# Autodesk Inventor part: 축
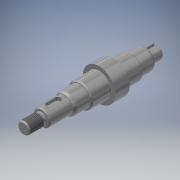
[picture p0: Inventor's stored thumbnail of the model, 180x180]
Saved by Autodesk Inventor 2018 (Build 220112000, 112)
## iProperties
Created: 2019-09
Part Number: 축
Material: 강철, 연강
Document SubType Name: Modeling
Designer: mduedu
Density: 7.86 g/cm^3
Mass: 210.278 g
Surface Area: 69.4764 cm^2
Volume: 26.7529 cm^3
Appearance: 강철
Author: mduedu
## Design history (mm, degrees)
sketch "스케치1"
  geometry: L1 (0, 0)-(15, 0); L2 (15, 0)-(15, 5); L3 (15, 5)-(0, 5); L4 (0, 5)-(0, 0); L5 (15, 0)-(34, 0); L6 (34, 0)-(34, 7); L7 (34, 7)-(15, 7); L8 (15, 7)-(15, 0); L9 (34, 0)-(47, 0); L10 (47, 0)-(47, 8.5); L11 (47, 8.5)-(34, 8.5); L12 (34, 8.5)-(34, 0); L13 (47, 0)-(63, 0); L14 (63, 0)-(63, 10); L15 (63, 10)-(47, 10); L16 (47, 10)-(47, 0); L17 (63, 0)-(75, 0); L18 (75, 0)-(75, 13.5); L19 (75, 13.5)-(63, 13.5); L20 (63, 13.5)-(63, 0); L21 (75, 0)-(90, 0); L22 (90, 0)-(90, 10); L23 (90, 10)-(75, 10); L24 (75, 10)-(75, 0); L25 (90, 0)-(102, 0); L26 (102, 0)-(102, 8.5); L27 (102, 8.5)-(90, 8.5); L28 (90, 8.5)-(90, 0); L29 (102, 0)-(111, 0); L30 (111, 0)-(111, 5.5); L31 (111, 5.5)-(102, 5.5); L32 (102, 5.5)-(102, 0)
  constraints: 64 end point, 16 parallel, 8 horizontal, 8 perpendicular
  dimensions: "d0" = 111 distance between parallel lines of L30 L4; "d2" = 15 distance of L2.end L3.end; "d3" = 19 distance of L6.end L7.end; "d4" = 12 distance of L18.end L19.end; "d5" = 15 distance of L22.end L23.end; "d6" = 12 distance of L26.end L27.end; "d7" = 9 distance of L30.end L31.end; "d8" = 16 distance of L14.end L15.end; "d9" = 10 diameter of L3 L1; "d10" = 14 diameter of L7 L5; "d11" = 17 diameter of L11 L9; "d12" = 20 diameter of L15 L13; "d13" = 27 diameter of L19 L17; "d14" = 20 diameter of L23 L21; "d15" = 17 diameter of L27 L25; "d16" = 11 diameter of L31 L29
revolve "회전1" sketch "스케치1" stored, may be unused: angle "d17" = 90 deg
sketch "스케치2"
  geometry: L1 (0, -5)-(0, 5) reference; L2 (0, 5)-(15, 5) reference; L3 (15, 5)-(15, 7) reference; L4 (15, 7)-(34, 7) reference; L5 (34, 7)-(34, 8.5) reference; L6 (34, 8.5)-(47, 8.5) reference; L7 (47, 8.5)-(47, 10) reference; L8 (47, 10)-(63, 10) reference; L9 (63, 10)-(63, 13.5) reference; L10 (63, 13.5)-(75, 13.5) reference; L11 (75, 13.5)-(75, 10) reference; L12 (75, 10)-(90, 10) reference; L13 (90, 10)-(90, 8.5) reference; L14 (90, 8.5)-(102, 8.5) reference; L15 (102, 8.5)-(102, 5.5) reference; L16 (102, 5.5)-(111, 5.5) reference; L17 (111, 5.5)-(111, -5.5) reference; L18 (111, -5.5)-(102, -5.5) reference; L19 (102, -5.5)-(102, -8.5) reference; L20 (102, -8.5)-(90, -8.5) reference; L21 (90, -8.5)-(90, -10) reference; L22 (90, -10)-(75, -10) reference; L23 (75, -10)-(75, -13.5) reference; L24 (75, -13.5)-(63, -13.5) reference; L25 (63, -13.5)-(63, -10) reference; L26 (63, -10)-(47, -10) reference; L27 (47, -10)-(47, -8.5) reference; L28 (47, -8.5)-(34, -8.5) reference; L29 (34, -8.5)-(34, -7) reference; L30 (34, -7)-(15, -7) reference; L31 (15, -7)-(15, -5) reference; L32 (15, -5)-(0, -5) reference; L33 (0, 0)-(111, 0); L34 (15, 5)-(12.014, 5); L35 (13.4, 4.2)-(15, 4.2); L36 (15, 4.2)-(15, 5); L37 (12.014, 5)-(13.4, 4.2)
  constraints: 10 end point, 1 horizontal, 1 midpoint, 1 parallel, 1 vertical
  dimensions: "d18" = 30 deg angle of L2 L37; "d19" = 8.4 diameter of L35 L33; "d21" = 2.986 distance from line of L34.end L36
revolve "회전2" sketch "스케치2" stored, may be unused: angle "d22" = 90 deg
fillet "모깎기1" dims "d23" = 0.6
feature "스레드1" dims "d24" = 10, "d25" = 0
chamfer "모따기1" distance "d26" = 1; stored, may be unused: second distance "d27" = 2, angle "d28" = 45 deg
chamfer "모따기2" distance "d29" = 1; stored, may be unused: second distance "d30" = 2, angle "d31" = 45 deg
chamfer "모따기3" distance "d32" = 1.819; stored, may be unused: second distance "d33" = 2, angle "d34" = 30 deg
fillet "모깎기2" dims "d35" = 2
chamfer "모따기4" distance "d36" = 1; stored, may be unused: second distance "d37" = 2, angle "d38" = 30 deg
fillet "모깎기3" dims "d39" = 0.3
chamfer "모따기5" distance "d40" = 1; stored, may be unused: second distance "d41" = 2, angle "d42" = 30 deg
chamfer "모따기6" distance "d43" = 1.819; stored, may be unused: second distance "d44" = 2, angle "d45" = 30 deg
chamfer "모따기7" distance "d46" = 0.5; stored, may be unused: second distance "d47" = 2, angle "d48" = 30 deg
fillet "모깎기4" dims "d49" = 2
node "작업 평면1"
sketch "스케치3" dims "d51" = 12
  geometry: L1 (3, -2.5)-(-4, -2.5); L2 (-4, -2.5)-(-4, 2.5); L3 (-4, 2.5)-(3, 2.5); L4 (3, 2.5)-(3, -2.5); L5 (-9.5, 7.45)-(-9.5, -7.45) reference; 3 further points
  constraints: 8 end point, 2 midpoint, 2 parallel, 2 vertical alignment, 1 horizontal, 1 horizontal alignment, 1 perpendicular, 4 other
  dimensions: "d50" = 3 dimension on L5; "d52" = 5 distance between parallel lines of L3 L1
extrude "돌출1" cut sketch "스케치3" distance "d53" = 3; taper "d54" = 0 deg
node "작업 평면3"
sketch "스케치4"
  geometry: L1 (-4.5, -5)-(-4.5, 5) reference; L2 (-4.5, -2)-(1.5, -2); L3 (1.5, -2)-(1.5, 2); L4 (1.5, 2)-(-4.5, 2); L5 (-4.5, 2)-(-4.5, -2); 3 further points
  constraints: 8 end point, 2 horizontal alignment, 2 midpoint, 2 parallel, 1 horizontal, 1 perpendicular, 1 point on line, 1 vertical alignment, 2 other
  dimensions: "d55" = 4 distance between parallel lines of L4 L2; "d57" = 8 dimension on L1
extrude "돌출2" cut sketch "스케치4" distance "d58" = 2.5; taper "d59" = 0 deg
sketch "스케치5"
  geometry: A1 r 5.5 centre (2, -3) between (0, 2.123) and (4, 2.123) reference; 2 further points
  constraints: 1 point on circle
hole "구멍1" sketch "스케치5" at (2, -8.5) diameter "d60" = 2.459; stored, may be unused: countersink angle "d64" = 90 deg, drill point angle "d66" = 118 deg; dims "d61" = 6, "d62" = 4, "d63" = 2, "d65" = 5
node "솔리드1"
node "절단 모서리 투영1"
